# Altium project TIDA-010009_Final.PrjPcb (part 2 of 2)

## Sheet Schematic2.SchDoc
size 431 x 279 mm; Date: Not shown in title block; ApprovedBy: Not shown in title block; CheckedBy: Not shown in title block; Author: Not shown in title block; CompanyName: Not shown in title block; Engineer: Not shown in title block; Organization: Not shown in title block; Address1: Not shown in title block; Address2: Not shown in title block; Address3: Not shown in title block; Address4: Not shown in title block; DocumentNumber: 1; Revision: Use project parameter SCH_Rev; SheetNumber: 3; SheetTotal: 4; PageSetup: Record=PageOptions¦CenterHorizontal=True¦CenterVertical=True¦PrintScale=1.00¦XCorrection=1.00¦YCorrection=1.00¦PrintKind=0¦BorderSize=5000000¦LeftOffset=0¦BottomOffset=0¦Orientation=2¦PaperLength=1000¦PaperWidth=1000¦Scale=100¦PaperSource=15¦PrintQuality=600¦MediaType=1¦DitherType=10¦PaperKind=Letter¦PrintScaleMode=1
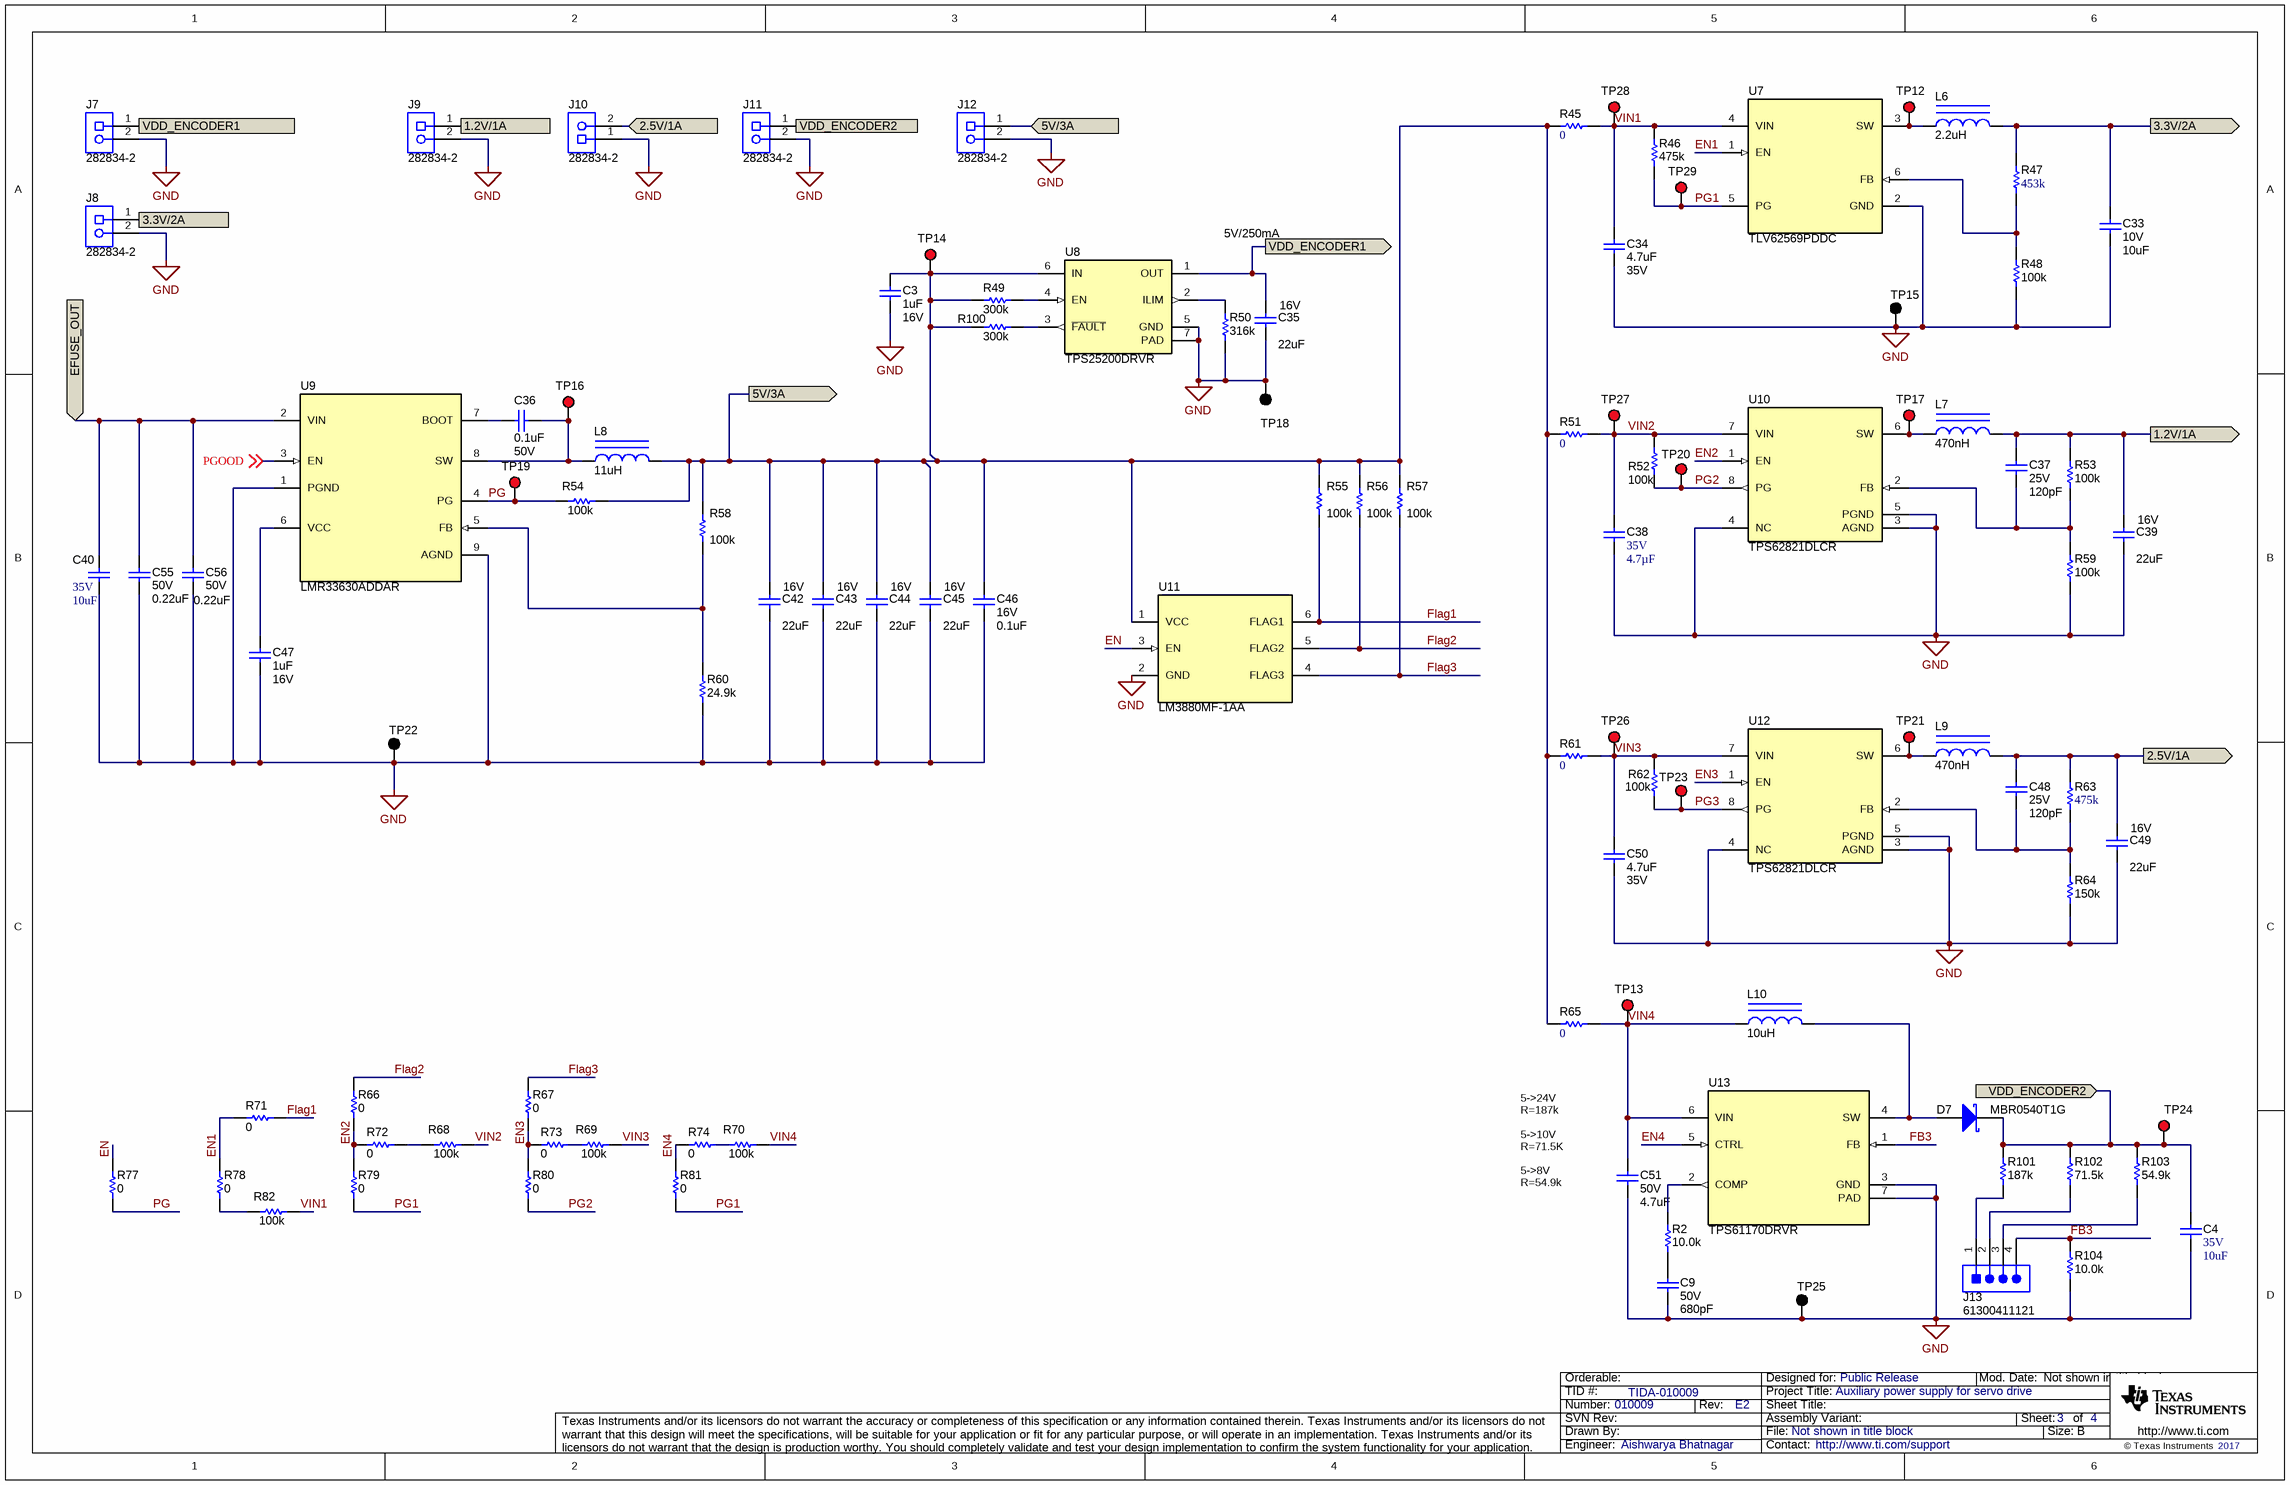
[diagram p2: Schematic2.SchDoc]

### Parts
C3  ValueDisplayed: 1uF  VDC_V: 16V  [0603]  (hidden comment: CMP-0006831-4)
C4  VDC_V: 35V  ValueDisplayed: 10uF  [1206_180]  (hidden comment: C3216X7R1V106K160AC)
C9  VDC_V: 50V  ValueDisplayed: 680pF  [0603]  (hidden comment: C0603C681K5RACTU)
C33  VDC_V: 10V  ValueDisplayed: 10uF  [0805_HV]  (hidden comment: GRM21BR71A106KE51L)
C34  ValueDisplayed: 4.7uF  VDC_V: 35V  [0805_HV]  (hidden comment: CMP-0007885-2)
C35  VDC_V: 16V  ValueDisplayed: 22uF  [1206_190]  (hidden comment: EMK316BB7226ML-T)
C36  ValueDisplayed: 0.1uF  VDC_V: 50V  [0603]  (hidden comment: CMP-0007044-5)
C37  VDC_V: 25V  ValueDisplayed: 120pF  [0201]  (hidden comment: GRM033R71E121KA01D)
C38  VDC_V: 35V  ValueDisplayed: 4.7µF  [1206_190]  (hidden comment: CGA5L1X7R1V475K160AE)
C39  VDC_V: 16V  ValueDisplayed: 22uF  [1206_190]  (hidden comment: EMK316BB7226ML-T)
C40  VDC_V: 35V  ValueDisplayed: 10uF  [1206_180]  (hidden comment: C3216X7R1V106K160AC)
C42  VDC_V: 16V  ValueDisplayed: 22uF  [1206_190]  (hidden comment: EMK316BB7226ML-T)
C43  VDC_V: 16V  ValueDisplayed: 22uF  [1206_190]  (hidden comment: EMK316BB7226ML-T)
C44  VDC_V: 16V  ValueDisplayed: 22uF  [1206_190]  (hidden comment: EMK316BB7226ML-T)
C45  VDC_V: 16V  ValueDisplayed: 22uF  [1206_190]  (hidden comment: EMK316BB7226ML-T)
C46  VDC_V: 16V  ValueDisplayed: 0.1uF  [0603]  (hidden comment: EMK107B7104KA-T)
C47  ValueDisplayed: 1uF  VDC_V: 16V  [0603]  (hidden comment: CMP-0006831-4)
C48  VDC_V: 25V  ValueDisplayed: 120pF  [0201]  (hidden comment: GRM033R71E121KA01D)
C49  VDC_V: 16V  ValueDisplayed: 22uF  [1206_190]  (hidden comment: EMK316BB7226ML-T)
C50  ValueDisplayed: 4.7uF  VDC_V: 35V  [0805_HV]  (hidden comment: CMP-0007885-2)
C51  VDC_V: 50V  ValueDisplayed: 4.7uF  [1206_190]  (hidden comment: UMK316AB7475KL-T)
C55  VDC_V: 50V  ValueDisplayed: 0.22uF  [0603]  (hidden comment: CGA3E3X7R1H224K080AB)
C56  VDC_V: 50V  ValueDisplayed: 0.22uF  [0603]  (hidden comment: CGA3E3X7R1H224K080AB)
D7  MBR0540T1G  [SOD-123]
J7  282834-2  [TEC_282834-2]
J8  282834-2  [TEC_282834-2]
J9  282834-2  [TEC_282834-2]
J10  282834-2  [TEC_282834-2]
J11  282834-2  [TEC_282834-2]
J12  282834-2  [TEC_282834-2]
J13  61300411121  [WURTH_61300411121]
L6  ValueDisplayed: 2.2uH  [LQH5BPN_20]  (hidden comment: LQH5BPN2R2NT0L)
L7  ValueDisplayed: 470nH  [XFL4015]  (hidden comment: XFL4015-471MEC)
L8  ValueDisplayed: 11uH  [WE-PDF_1064]  (hidden comment: 7447798111)
L9  ValueDisplayed: 470nH  [XFL4015]  (hidden comment: XFL4015-471MEC)
L10  ValueDisplayed: 10uH  [FDSD0420]  (hidden comment: FDSD0420-H-100M)
R2  ValueDisplayed: 10.0k  [0603]  (hidden comment: RG1608P-103-B-T5)
R45  ValueDisplayed: 0  [0805_HV]  (hidden comment: ERJ-6GEY0R00V)
R46  ValueDisplayed: 475k  [0805_HV]  (hidden comment: RR1220P-4753-D-M)
R47  ValueDisplayed: 453k  [0603]  (hidden comment: RT0603DRE07453KL)
R48  ValueDisplayed: 100k  [0603]  (hidden comment: ERA-3AEB104V)
R49  ValueDisplayed: 300k  [0603]  (hidden comment: RG1608P-304-B-T5)
R50  ValueDisplayed: 316k  [0603]  (hidden comment: RC0603FR-07316KL)
R51  ValueDisplayed: 0  [0805_HV]  (hidden comment: ERJ-6GEY0R00V)
R52  ValueDisplayed: 100k  [0603]  (hidden comment: ERA-3AEB104V)
R53  ValueDisplayed: 100k  [0603]  (hidden comment: ERA-3AEB104V)
R54  ValueDisplayed: 100k  [0603]  (hidden comment: ERA-3AEB104V)
R55  ValueDisplayed: 100k  [0603]  (hidden comment: ERA-3AEB104V)
R56  ValueDisplayed: 100k  [0603]  (hidden comment: ERA-3AEB104V)
R57  ValueDisplayed: 100k  [0603]  (hidden comment: ERA-3AEB104V)
R58  ValueDisplayed: 100k  [0603]  (hidden comment: ERA-3AEB104V)
R59  ValueDisplayed: 100k  [0603]  (hidden comment: ERA-3AEB104V)
R60  ValueDisplayed: 24.9k  [0603]  (hidden comment: RT0603BRD0724K9L)
R61  ValueDisplayed: 0  [0805_HV]  (hidden comment: ERJ-6GEY0R00V)
R62  ValueDisplayed: 100k  [0603]  (hidden comment: ERA-3AEB104V)
R63  ValueDisplayed: 475k  [0603]  (hidden comment: RT0603DRE07475KL)
R64  ValueDisplayed: 150k  [0603]  (hidden comment: RT0603BRD07150KL)
R65  ValueDisplayed: 0  [0805_HV]  (hidden comment: ERJ-6GEY0R00V)
R66  ValueDisplayed: 0  [0603]  (hidden comment: RMCF0603ZT0R00)
R67  ValueDisplayed: 0  [0603]  (hidden comment: RMCF0603ZT0R00)
R68  ValueDisplayed: 100k  [0603]  (hidden comment: ERA-3AEB104V)
R69  ValueDisplayed: 100k  [0603]  (hidden comment: ERA-3AEB104V)
R70  ValueDisplayed: 100k  [0603]  (hidden comment: ERA-3AEB104V)
R71  ValueDisplayed: 0  [0603]  (hidden comment: RMCF0603ZT0R00)
R72  ValueDisplayed: 0  [0603]  (hidden comment: RMCF0603ZT0R00)
R73  ValueDisplayed: 0  [0603]  (hidden comment: RMCF0603ZT0R00)
R74  ValueDisplayed: 0  [0603]  (hidden comment: RMCF0603ZT0R00)
R77  ValueDisplayed: 0  [0603]  (hidden comment: RMCF0603ZT0R00)
R78  ValueDisplayed: 0  [0603]  (hidden comment: RMCF0603ZT0R00)
R79  ValueDisplayed: 0  [0603]  (hidden comment: RMCF0603ZT0R00)
R80  ValueDisplayed: 0  [0603]  (hidden comment: RMCF0603ZT0R00)
R81  ValueDisplayed: 0  [0603]  (hidden comment: RMCF0603ZT0R00)
R82  ValueDisplayed: 100k  [0603]  (hidden comment: ERA-3AEB104V)
R100  ValueDisplayed: 300k  [0603]  (hidden comment: RG1608P-304-B-T5)
R101  ValueDisplayed: 187k  [0603]  (hidden comment: CRCW0603187KFKEA)
R102  ValueDisplayed: 71.5k  [0603]  (hidden comment: CRCW060371K5FKEA)
R103  ValueDisplayed: 54.9k  [0603]  (hidden comment: CRCW060354K9FKEA)
R104  ValueDisplayed: 10.0k  [0603]  (hidden comment: RG1608P-103-B-T5)
TP12  5000  [Keystone5000]  (value not drawn)
TP13  5000  [Keystone5000]  (value not drawn)
TP14  5000  [Keystone5000]  (value not drawn)
TP15  5001  [Keystone5001]  (value not drawn)
TP16  5000  [Keystone5000]  (value not drawn)
TP17  5000  [Keystone5000]  (value not drawn)
TP18  5001  [Keystone5001]  (value not drawn)
TP19  5000  [Keystone5000]  (value not drawn)
TP20  5000  [Keystone5000]  (value not drawn)
TP21  5000  [Keystone5000]  (value not drawn)
TP22  5001  [Keystone5001]  (value not drawn)
TP23  5000  [Keystone5000]  (value not drawn)
TP24  5000  [Keystone5000]  (value not drawn)
TP25  5001  [Keystone5001]  (value not drawn)
TP26  5000  [Keystone5000]  (value not drawn)
TP27  5000  [Keystone5000]  (value not drawn)
TP28  5000  [Keystone5000]  (value not drawn)
TP29  5000  [Keystone5000]  (value not drawn)
U7  TLV62569PDDC  [DDC0006A_N]
U8  TPS25200DRVR  [DRV0006A]
U9  LMR33630ADDAR  [DDA0008J]
U10  TPS62821DLCR  [DLC0008A]
U11  LM3880MF-1AA  [DBV0006A_N]
U12  TPS62821DLCR  [DLC0008A]
U13  TPS61170DRVR  [DRV0006A]

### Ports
1.2V/1A (in), 1.2V/1A (out), 2.5V/1A (in), 2.5V/1A (out), 3.3V/2A (in), 3.3V/2A (out), 5V/3A (in), 5V/3A (out), EFUSE_OUT (in), VDD_ENCODER1 (in), VDD_ENCODER1 (out), VDD_ENCODER2 (in)

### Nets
GND: C3.2 C4.2 C9.2 C33.2 C34.2 C35.2 C38.2 C39.2 C40.2 C42.2 C43.2 C44.2 C45.2 C46.2 C47.2 C49.2 C50.2 C51.2 C55.2 C56.2 J7.2 J8.2 J9.2 J10.1 J11.2 J12.2 R48.1 R50.1 R59.1 R60.1 R64.1 R104.1 TP15.1 TP18.1 TP22.1 TP25.1 U7.2(GND) U8.5(GND) U8.7(PAD) U9.1(PGND) U9.9(AGND) U10.3(AGND) U10.4(NC) U10.5(PGND) U11.2(GND) U12.3(AGND) U12.4(NC) U12.5(PGND) U13.3(GND) U13.7(PAD)
1.2V/1A: C37.1 C39.1 J9.1 L7.2 R53.2 ; port 1.2V/1A
2.5V/1A: C48.1 C49.1 J10.2 L9.2 R63.2 ; port 2.5V/1A
3.3V/2A: C33.1 J8.1 L6.2 R47.2 ; port 3.3V/2A
5V/3A: C3.1 C42.1 C43.1 C44.1 C45.1 C46.1 J12.1 L8.2 R45.1 R49.1 R51.1 R54.1 R55.2 R56.2 R57.2 R58.2 R61.1 R65.1 R100.1 TP14.1 U8.6(IN) U11.1(VCC) ; port 5V/3A
EFUSE_OUT: C40.1 C55.1 C56.1 U9.2(VIN) ; port EFUSE_OUT
EN: R77.1 U11.3(EN)
EN1: R71.1 R78.1 U7.1(EN)
EN2: R66.2 R72.1 R79.1 U10.1(EN)
EN3: R67.2 R73.1 R80.1 U12.1(EN)
EN4: R74.1 R81.1 U13.5(CTRL)
FB3: J13.4 R104.2 U13.1(FB)
Flag1: R55.1 R71.2 U11.6(FLAG1)
Flag2: R56.1 R66.1 U11.5(FLAG2)
Flag3: R57.1 R67.1 U11.4(FLAG3)
PG: R54.2 R77.2 TP19.1 U9.4(PG)
PG1: R46.1 R79.2 R81.2 TP29.1 U7.5(PG)
PG2: R52.2 R80.2 TP20.1 U10.8(PG)
PG3: R62.2 TP23.1 U12.8(PG)
PGOOD: U9.3(EN) ; off-sheet PGOOD
VDD_ENCODER1: C35.1 J7.1 U8.1(OUT) ; port VDD_ENCODER1
VDD_ENCODER2: C4.1 D7.1(K) J11.1 R101.2 R102.2 R103.2 TP24.1 ; port VDD_ENCODER2
VIN1: C34.1 R45.2 R46.2 R82.1 TP28.1 U7.4(VIN)
VIN2: C38.1 R51.2 R52.1 R68.1 TP27.1 U10.7(VIN)
VIN3: C50.1 R61.2 R62.1 R69.1 TP26.1 U12.7(VIN)
VIN4: C51.1 L10.1 R65.2 R70.1 TP13.1 U13.6(VIN)
NetC9_1: C9.1 R2.1
NetC36_1: C36.1 U9.7(BOOT)
NetC36_2: C36.2 L8.1 TP16.1 U9.8(SW)
NetC37_2: C37.2 R53.1 R59.2 U10.2(FB)
NetC47_1: C47.1 U9.6(VCC)
NetC48_2: C48.2 R63.1 R64.2 U12.2(FB)
NetD7_2: D7.2(A) L10.2 U13.4(SW)
NetJ13_1: J13.1 R101.1
NetJ13_2: J13.2 R102.1
NetJ13_3: J13.3 R103.1
NetL6_1: L6.1 TP12.1 U7.3(SW)
NetL7_1: L7.1 TP17.1 U10.6(SW)
NetL9_1: L9.1 TP21.1 U12.6(SW)
NetR2_2: R2.2 U13.2(COMP)
NetR47_1: R47.1 R48.2 U7.6(FB)
NetR49_2: R49.2 U8.4(EN)
NetR50_2: R50.2 U8.2(ILIM)
NetR58_1: R58.1 R60.2 U9.5(FB)
NetR68_2: R68.2 R72.2
NetR69_2: R69.2 R73.2
NetR70_2: R70.2 R74.2
NetR78_2: R78.2 R82.2
NetR100_2: R100.2 U8.3(~{FAULT})

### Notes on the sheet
- 5V/250mA
- (near C51) 5->24V
  R=187k
  5->10V
  R=71.5K
  5->8V
  R=54.9k

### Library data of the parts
C3 C47 = CMP-0006831-4: CAP, CERM, 1 uF, 16 V, +/- 10%, X7R, 0603; PartNumber: 885012206052; Manufacturer: Wurth Elektronik; Polarized: N; Value: 1uF; U/M: EA; Cap_F: 1µF; Value1: Unknown; TaMin_C: -55°C; TaMax_C: 125°C; SizeArea_mm2: 1.28; SizeAreaWB_mm2: 4.68; SizeX_mm: 1.6; SizeY_mm: 0.8; SizeZ_mm: 1; AEC Category: Q200
C4 C40 = CMP-0008705-2: CAP, CERM, 10 uF, 35 V, +/- 10%, X7R, 1206; Manufacturer: TDK; TaMin_C: -55°C; ESR_ohm: 2.229m; Polarized: N; SizeAreaWB_mm2: 10.92; Value1: 0.002229 ohm; U/M: EA; Value: 10uF; TaMax_C: 125°C; SizeZ_mm: 1.8; SizeX_mm: 3.2; SizeY_mm: 1.6; SizeArea_mm2: 5.12; Cap_F: 10µF; IRMS_A: 4.85932A; AEC Category: Q200
C9 = CMP-0006960-4: CAP, CERM, 680 pF, 50 V, +/- 10%, X7R, 0603; Manufacturer: Kemet; TaMin_C: -55°C; Polarized: N; SizeAreaWB_mm2: 4.68; Value1: Unknown; U/M: EA; Value: 680pF; TaMax_C: 125°C; SizeZ_mm: 1; SizeX_mm: 1.6; SizeY_mm: 0.8; SizeArea_mm2: 1.28; AEC Category: Q200
C33 = CMP-0008315-2: CAP, CERM, 10 uF, 10 V, +/- 10%, X7R, 0805; Manufacturer: MuRata; TaMin_C: -55°C; ESR_ohm: 3m; Polarized: N; SizeAreaWB_mm2: 6.75; Value1: 0.003 ohm; U/M: EA; Value: 10uF; TaMax_C: 125°C; SizeZ_mm: 1.45; SizeX_mm: 2; SizeY_mm: 1.25; Cap_Case: 0805; SizeArea_mm2: 2.5; CompType: Capacitor; Cap_F: 10µF; AEC Category: Q200
C34 C50 = CMP-0007885-2: CAP, CERM, 4.7 uF, 35 V, +/- 10%, X7R, 0805; PartNumber: C2012X7R1V475K125AC; Manufacturer: TDK; Polarized: N; Value: 4.7uF; U/M: EA; Cap_F: 4.7µF; ESR_ohm: 2.346m; Value1: 0.002346 ohm; IRMS_A: 4.26021A; TaMin_C: -55°C; TaMax_C: 125°C; Cap_Case: 0805; AEC Category: Q200; SizeArea_mm2: 2.5; SizeAreaWB_mm2: 6.75; SizeX_mm: 2; SizeY_mm: 1.25; SizeZ_mm: 1.45
C35 C39 C42-C45 C49 = CMP-0008805-2: CAP, CERM, 22 uF, 16 V, +/- 20%, X7R, 1206_190; Manufacturer: Taiyo Yuden; TaMin_C: -55°C; Polarized: N; SizeAreaWB_mm2: 10.92; Value1: Unknown; U/M: EA; Value: 22uF; TaMax_C: 125°C; SizeZ_mm: 1.9; SizeX_mm: 3.2; SizeY_mm: 1.6; Cap_Case: 1206; SizeArea_mm2: 5.12; Cap_F: 22µF; AEC Category: Q200
C36 = CMP-0007044-5: CAP, CERM, 0.1 uF, 50 V, +/- 10%, X7R, 0603; PartNumber: C1608X7R1H104K080AA; Manufacturer: TDK; Polarized: N; CompType: Capacitor; Value: 0.1uF; U/M: EA; Cap_F: 100nF; ESR_ohm: 0.0296; Value1: 0.0296 ohm; IRMS_A: 9.7199dA; TaMin_C: -55°C; TaMax_C: 125°C; SizeArea_mm2: 1.28; SizeAreaWB_mm2: 4.68; SizeX_mm: 1.6; SizeY_mm: 0.8; SizeZ_mm: 1; AEC Category: Q200
C37 C48 = CMP-0009765-1: CAP, CERM, 120 pF, 25 V, +/- 10%, X7R, 0201; Manufacturer: MuRata; TaMin_C: -55°C; Polarized: N; SizeAreaWB_mm2: 2.08; Value1: Unknown; U/M: EA; Value: 120pF; TaMax_C: 125°C; SizeZ_mm: 0.26; SizeX_mm: 0.6; SizeY_mm: 0.3; SizeArea_mm2: 0.18; AEC Category: Q200
C38 = CMP-0081201-1: CAP, CERM, 4.7 µF, 35 V,+/- 10%, X7R, AEC-Q200 Grade 1, 1206; Manufacturer: TDK; TaMin_C: -55°C; Polarized: N; SizeAreaWB_mm2: 10.92; U/M: EA; Value: 4.7uF; TaMax_C: 125°C; SizeZ_mm: 1.9; SizeX_mm: 3.2; SizeY_mm: 1.6; Cap_Case: 1206; SizeArea_mm2: 5.12; AEC Qualified: Y; AEC Grade: 1; AEC Category: Q200
C46 = CMP-0007119-4: CAP, CERM, 0.1 uF, 16 V, +/- 10%, X7R, 0603; Manufacturer: Taiyo Yuden; TaMin_C: -55°C; Polarized: N; SizeAreaWB_mm2: 4.68; Value1: Unknown; U/M: EA; Value: 0.1uF; TaMax_C: 125°C; SizeZ_mm: 1; SizeX_mm: 1.6; SizeY_mm: 0.8; SizeArea_mm2: 1.28; CompType: Capacitor; Cap_F: 100nF; AEC Category: Q200
C51 = CMP-0009026-2: CAP, CERM, 4.7 uF, 50 V, +/- 10%, X7R, 1206_190; Manufacturer: Taiyo Yuden; TaMin_C: -55°C; Polarized: N; SizeAreaWB_mm2: 10.92; Value1: Unknown; U/M: EA; Value: 4.7uF; TaMax_C: 125°C; SizeZ_mm: 1.9; SizeX_mm: 3.2; SizeY_mm: 1.6; Cap_Case: 1206; SizeArea_mm2: 5.12; CompType: Capacitor; Cap_F: 4.7µF; AEC Category: Q200
C55 C56 = CMP-0007094-5: CAP, CERM, 0.22 uF, 50 V, +/- 10%, X7R, AEC-Q200 Grade 1, 0603; Manufacturer: TDK; TaMin_C: -55°C; ESR_ohm: 0.021699; Polarized: N; SizeAreaWB_mm2: 4.68; Value1: 0.021699 ohm; U/M: EA; Value: 0.22uF; TaMax_C: 125°C; SizeZ_mm: 1; SizeX_mm: 1.6; SizeY_mm: 0.8; SizeArea_mm2: 1.28; AEC Qualified: Y; Cap_F: 220nF; IRMS_A: 1.12496A; AEC Category: Q200
D7 = CMP-0028526-2: Diode, Schottky, 40 V, 0.5 A, SOD-123; Manufacturer: ON Semiconductor; Green_REACh: Passed; SizeY_mm: 1.7; Io_A: 5dA; SizeArea_mm2: 6.545; RJC_CperW: 118; Green_Lifecycle: Active; Vr_V: 40V; Vf_V: 5.1dV; TJmax_C: 150°C; AEC Category: Q101; SizeAreaWB_mm2: 13.095; Value1: 0.5A; SizeZ_mm: 1.35; SizeX_mm: 3.85; Value2: 0.51V; Value: 40V
J7-J12 = CMP-0054974-1: Terminal Block, 2x1, 2.54mm, TH; Manufacturer: TE Connectivity; CNHeader: FALSE; Green_Lifecycle: Active; Green_REACh: Passed; CT: TRUE
J13 = CMP-0054798-1: Header, 2.54 mm, 4x1, Gold, TH; Manufacturer: Wurth Elektronik; CNHeader: TRUE; CT: FALSE
L6 = CMP-0058727-1: Inductor, Wirewound, Ferrite, 2.2 uH, 2.6 A, 0.036 ohm, SMD; Manufacturer: MuRata; Isat: 4A @ 30% inductance drop; Irms: 2.6A @ 40C rise; SizeAreaWB_mm2: 34.81; DCR_ohm: 0.036; Value: 2.2uH; Imax_A: 2.6A; SizeZ_mm: 2.2; SizeX_mm: 4.9; SizeArea_mm2: 24.01; Ind_H: 2.2µH; AEC Qualified: N; AEC Category: Q200
L7 L9 = CMP-0061147-1: Inductor, Shielded, Composite, 470 nH, 3.5 A, 0.0076 ohm, SMD; Manufacturer: Coilcraft; Isat: 3.5A @ 10% inductance drop; Irms: 9.1A @ 20C rise; Green_Lifecycle: Not Set; SizeAreaWB_mm2: 28.09; DCR_ohm: 7.6m; Green_REACh: Incomplete; Value: 470nH; Imax_A: 3.5A; SizeZ_mm: 1.6; SizeX_mm: 4.3; SizeArea_mm2: 18.49; AEC Category: Q200
L8 = CMP-0064666-2: Inductor, Shielded, Metal Composite, 11 uH, 5.3 A, 0.014 ohm, SMD; Manufacturer: Wurth Elektronik; Isat: 5.3A @ 10% inductance drop; Irms: 6.9A @ 40C rise; Green_Lifecycle: Active; SizeAreaWB_mm2: 148.84; DCR_ohm: 0.014; Green_REACh: Passed; Value: 11uH; Imax_A: 5.3A; SizeZ_mm: 6.4; SizeX_mm: 10.2; SizeArea_mm2: 104.04; Ind_H: 11µH; AEC Category: Q200
L10 = CMP-0058995-1: Inductor, Shielded, Powdered Iron, 10 uH, 2 A, 0.2 ohm, SMD; Manufacturer: MuRata Toko; Isat: 3.3A @ 30% inductance drop; Irms: 2A @ 40C rise; Green_Lifecycle: Not Set; SizeAreaWB_mm2: 27.04; DCR_ohm: 2d; Green_REACh: Incomplete; Value1: 0.2 ohm; Value: 10uH; Imax_A: 2A; SizeZ_mm: 2; SizeX_mm: 4.2; SizeArea_mm2: 17.64; Ind_H: 10µH; AEC Category: Q200
R2 R104 = CMP-0023404-3: RES, 10.0 k, 0.1%, 0.1 W, 0603; Manufacturer: Susumu Co Ltd; Power_W: 100mW; TempCo: 25 ppm/C; Value_Code: 10k0; U/M: EA; Value: 10.0k; EIA_Code: E192; Res_ohm: 10k; SizeX_mm: 1.6; SizeY_mm: 0.8; SizeZ_mm: 1; Value2: 0.1W; SizeArea_mm2: 1.28; VDC_V: 75V; AEC Category: Q200
R45 R51 R61 R65 = CMP-0020616-3: RES, 0, 5%, 0.125 W, AEC-Q200 Grade 0, 0805; Manufacturer: Panasonic; Power_W: 125mW; TempCo: 600 ppm/C; Value_Code: 0000; Value: 0; EIA_Code: E24; SizeX_mm: 2; SizeY_mm: 1.25; SizeZ_mm: 1.45; Value2: 0.125W; SizeArea_mm2: 2.5; AEC Qualified: Y; VDC_V: 150V; AEC Category: Q200; SizeAreaWB_mm2: 6.75
R46 = CMP-0019302-2: RES, 475 k, 0.5%, 0.1 W, 0805; Manufacturer: Susumu Co Ltd; Power_W: 100mW; TempCo: 25 ppm/C; U/M: EA; Value: 475k; EIA_Code: E192; SizeX_mm: 2; SizeY_mm: 1.25; SizeZ_mm: 1.45; Value2: 0.1W; SizeArea_mm2: 2.5; VDC_V: 100V; AEC Category: Q200
R47 = CMP-0025299-2: RES, 453 k, 0.5%, 0.1 W, 0603; Manufacturer: Yageo America; Power_W: 100mW; TempCo: 50 ppm/C; U/M: EA; Value: 453k; EIA_Code: E192; SizeX_mm: 1.6; SizeY_mm: 0.8; SizeZ_mm: 1; Value2: 0.1W; SizeArea_mm2: 1.28; VDC_V: 75V; AEC Category: Q200
R48 R52-R59 R62 R68 R70 R82 = CMP-0023363-3: RES, 100 k, 0.1%, 0.1 W, AEC-Q200 Grade 0, 0603; Manufacturer: Panasonic; Power_W: 100mW; TempCo: 25 ppm/C; U/M: EA; Value: 100k; EIA_Code: E192; SizeX_mm: 1.6; SizeY_mm: 0.8; SizeZ_mm: 1; Value2: 0.1W; SizeArea_mm2: 1.28; AEC Qualified: Y; VDC_V: 75V; AEC Grade: 0; AEC Category: Q200
R49 R100 = CMP-0023509-3: RES, 300 k, 0.1%, 0.1 W, 0603; Manufacturer: Susumu Co Ltd; Power_W: 100mW; TempCo: 25 ppm/C; U/M: EA; Value: 300k; SizeX_mm: 1.6; SizeY_mm: 0.8; SizeZ_mm: 1; Value2: 0.1W; SizeArea_mm2: 1.28; VDC_V: 75V; AEC Category: Q200
R50 = CMP-0023024-4: RES, 316 k, 1%, 0.1 W, 0603; Manufacturer: Yageo; Power_W: 100mW; TempCo: 100 ppm/C; Value: 316k; EIA_Code: E96; SizeX_mm: 1.6; SizeY_mm: 0.8; SizeZ_mm: 1; Value2: 0.1W; SizeArea_mm2: 1.28; AEC Qualified: N; VDC_V: 75V; AEC Category: Q200; SizeAreaWB_mm2: 4.68
R60 = CMP-0023990-3: RES, 24.9 k, 0.1%, 0.1 W, 0603; Manufacturer: Yageo America; Power_W: 100mW; TempCo: 25 ppm/C; Value_Code: 24k9; U/M: EA; Value: 24.9k; EIA_Code: E192; SizeX_mm: 1.6; SizeY_mm: 0.8; SizeZ_mm: 1; Value2: 0.1W; SizeArea_mm2: 1.28; CompType: Resistor; VDC_V: 75V; AEC Category: Q200
R63 = CMP-0025313-3: RES, 475 k, 0.5%, 0.1 W, 0603; Manufacturer: Yageo America; Power_W: 100mW; TempCo: 50 ppm/C; U/M: EA; Value: 475k; EIA_Code: E192; SizeX_mm: 1.6; SizeY_mm: 0.8; SizeZ_mm: 1; Value2: 0.1W; SizeArea_mm2: 1.28; VDC_V: 75V; AEC Category: Q200
R64 = CMP-0023766-3: RES, 150 k, 0.1%, 0.1 W, 0603; Manufacturer: Yageo America; Power_W: 100mW; TempCo: 25 ppm/C; U/M: EA; Value: 150k; EIA_Code: E192; SizeX_mm: 1.6; SizeY_mm: 0.8; SizeZ_mm: 1; Value2: 0.1W; SizeArea_mm2: 1.28; VDC_V: 75V; AEC Category: Q200
R66 R67 R71-R74 R77-R81 = CMP-0023343-3: RES, 0, 1%, 0.1 W, AEC-Q200 Grade 0, 0603; Manufacturer: Stackpole Electronics Inc; Power_W: 100mW; TempCo: ppm/C; U/M: EA; Value: 0; SizeX_mm: 1.6; SizeY_mm: 0.8; SizeZ_mm: 1; Value2: 0.1W; SizeArea_mm2: 1.28; AEC Qualified: Y; AEC Category: Q200
R69 = CMP-0023363-3: RES, 100 k, 0.1%, 0.1 W, AEC-Q200 Grade 0, 0603; Manufacturer: Panasonic; Power_W: 100mW; TempCo: 25 ppm/C; U/M: EA; Value: 100k; EIA_Code: E192; SizeX_mm: 1.6; SizeY_mm: 0.8; SizeZ_mm: 1; Value2: 0.1W; SizeArea_mm2: 1.28; CompType: Resistor; AEC Qualified: Y; VDC_V: 75V; AEC Grade: 0; AEC Category: Q200
R101 = CMP-0022095-4: RES, 187 k, 1%, 0.1 W, AEC-Q200 Grade 0, 0603; Manufacturer: Vishay-Dale; Power_W: 100mW; TempCo: 100 ppm/C; Value: 187k; EIA_Code: E96; SizeX_mm: 1.6; SizeY_mm: 0.8; SizeZ_mm: 1; Value2: 0.1W; SizeArea_mm2: 1.28; AEC Qualified: Y; VDC_V: 75V; AEC Category: Q200; AEC Grade: 0
R102 = CMP-0022581-4: RES, 71.5 k, 1%, 0.1 W, AEC-Q200 Grade 0, 0603; Manufacturer: Vishay-Dale; Power_W: 100mW; TempCo: 100 ppm/C; Value_Code: 71k5; Value: 71.5k; EIA_Code: E96; SizeX_mm: 1.6; SizeY_mm: 0.8; SizeZ_mm: 1; Value2: 0.1W; SizeArea_mm2: 1.28; AEC Qualified: Y; VDC_V: 75V; AEC Category: Q200; AEC Grade: 0
R103 = CMP-0022494-4: RES, 54.9 k, 1%, 0.1 W, AEC-Q200 Grade 0, 0603; Manufacturer: Vishay-Dale; Power_W: 100mW; TempCo: 100 ppm/C; Value_Code: 54k9; Value: 54.9k; EIA_Code: E96; SizeX_mm: 1.6; SizeY_mm: 0.8; SizeZ_mm: 1; Value2: 0.1W; SizeArea_mm2: 1.28; AEC Qualified: Y; VDC_V: 75V; AEC Category: Q200; AEC Grade: 0
TP12-TP14 TP16 TP17 TP19-TP21 TP23 TP24 TP26-TP29 = CMP-0055137-1: Test Point, Miniature, Red, TH; Manufacturer: Keystone; CNHeader: FALSE; Green_Lifecycle: Active; Green_REACh: Passed; ContactFinish: Silver; CT: TRUE
TP15 TP18 TP22 TP25 = CMP-0055138-1: Test Point, Miniature, Black, TH; Manufacturer: Keystone; CNHeader: FALSE; Green_Lifecycle: Active; Green_REACh: Passed; ContactFinish: Silver; CT: TRUE
U7 = CMP-0013280-3: 2-A High Efficiency Step-Down Converter in SOT Package, DDC0006A (SOT-6); Manufacturer: Texas Instruments; SizeZ_mm: 0.87; SizeX_mm: 1.65; SizeY_mm: 2.95; SizeArea_mm2: 4.8675; CompType: IC; U/M: EA; SizeAreaWB_mm2: 10.4675
U8 = CMP-0074216-4: 6.5 V/2.8 A eFuse with Overvoltage Clamp, DRV0006A (WSON-6); Manufacturer: Texas Instruments; Alternate PartNumber: TPS25200DRVT; SizeX_mm: 2; CompType: IC; SizeZ_mm: 0.8; SizeArea_mm2: 4; SizeAreaWB_mm2: 9; U/M: EA; Green_Lifecycle: Active; Green_REACh: Passed
U9 = CMP-0013272-2: SIMPLE SWITCHER 3.8V to 36V 3A/2A Synchronous Step-Down Voltage Regulator, DDA0008J (SOIC-8); Manufacturer: Texas Instruments; SizeX_mm: 5.99; SizeY_mm: 4.89; CompType: IC; SizeZ_mm: 1.7; SizeArea_mm2: 29.2911; SizeAreaWB_mm2: 55.0511; U/M: EA
U10 U12 = CMP-0065148-3: 1A Step-Down Converter With 1% Accuracy, DLC0008A (VSON-HR-8); Manufacturer: Texas Instruments; SizeX_mm: 1.5; SizeY_mm: 2.0; CompType: IC; SizeZ_mm: 1.0; SizeArea_mm2: 3.0; SizeAreaWB_mm2: 7.5; AEC Category: Q200; AEC Qualified: N
U11 = CMP-0071684-1: Power Sequencer, 6-pin SOT-23, 1000 Reel; Manufacturer: Texas Instruments; CompType: MiscPower; PackageTopMarking: F20A*XTT; High-Reliability: Y; PowerWise: N
U13 = CMP-0067200-5: 1.2A Switch, High Voltage Boost Converter in 2x2mm QFN Package, DRV0006A (WSON-6); Manufacturer: Texas Instruments; Alternate PartNumber: TPS61170DRVT; SizeX_mm: 2; CompType: IC; SizeZ_mm: 0.8; SizeArea_mm2: 4; SizeAreaWB_mm2: 9; U/M: EA; Green_Lifecycle: Active; Green_REACh: Passed

## Sheet TIDA-010009_EVM_Hardware.SchDoc
size 431 x 279 mm; Date: Not shown in title block; ApprovedBy: Not shown in title block; CheckedBy: Not shown in title block; Author: Not shown in title block; CompanyName: Not shown in title block; Engineer: Not shown in title block; Organization: Not shown in title block; Address1: Not shown in title block; Address2: Not shown in title block; Address3: Not shown in title block; Address4: Not shown in title block; DocumentNumber: 1; Revision: Use project parameter SCH_Rev; SheetNumber: 4; SheetTotal: 4; PageSetup: Record=PageOptions¦CenterHorizontal=True¦CenterVertical=True¦PrintScale=1.00¦XCorrection=1.00¦YCorrection=1.00¦PrintKind=0¦BorderSize=5000000¦LeftOffset=0¦BottomOffset=0¦Orientation=2¦PaperLength=1000¦PaperWidth=1000¦Scale=100¦PaperSource=15¦PrintQuality=600¦MediaType=1¦DitherType=10¦PaperKind=Letter¦PrintScaleMode=1
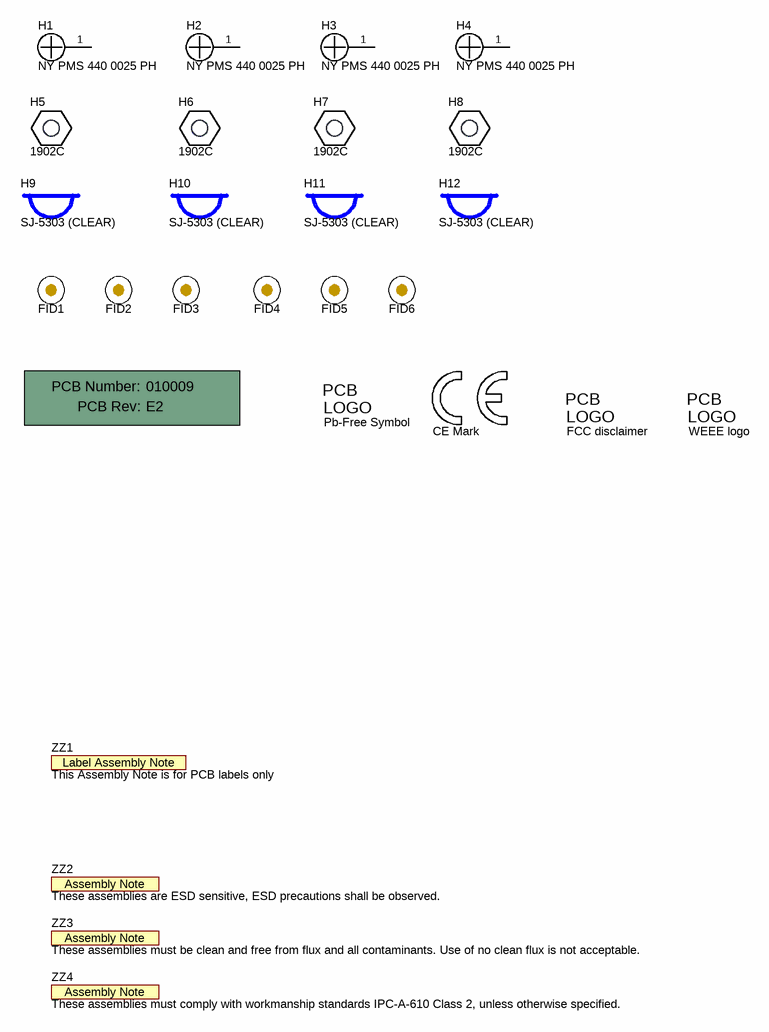
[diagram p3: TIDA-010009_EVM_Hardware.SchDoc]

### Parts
!PCB1  Printed Circuit Board  (value not drawn)  (mechanical)
FID1  Fiducial  [Fiducial10-20]  (value not drawn)
FID2  Fiducial  [Fiducial10-20]  (value not drawn)
FID3  Fiducial  [Fiducial10-20]  (value not drawn)
FID4  Fiducial  [Fiducial10-20]  (value not drawn)
FID5  Fiducial  [Fiducial10-20]  (value not drawn)
FID6  Fiducial  [Fiducial10-20]  (value not drawn)
H1  NY PMS 440 0025 PH  [NY PMS 440 0025 PH]
H2  NY PMS 440 0025 PH  [NY PMS 440 0025 PH]
H3  NY PMS 440 0025 PH  [NY PMS 440 0025 PH]
H4  NY PMS 440 0025 PH  [NY PMS 440 0025 PH]
H5  1902C  [Keystone_1902C]
H6  1902C  [Keystone_1902C]
H7  1902C  [Keystone_1902C]
H8  1902C  [Keystone_1902C]
H9  SJ-5303 (CLEAR)  [Bumpon_SJ5003Transparent]
H10  SJ-5303 (CLEAR)  [Bumpon_SJ5003Transparent]
H11  SJ-5303 (CLEAR)  [Bumpon_SJ5003Transparent]
H12  SJ-5303 (CLEAR)  [Bumpon_SJ5003Transparent]
Logo1  CE Mark  [CE_Mark_5mm]  (no BOM)
Logo3  FCC disclaimer  [FCC_disclaimer]  (no BOM)
Logo4  WEEE logo  [WEEE_Minimum]  (no BOM)
Logo5  Pb-Free Symbol  [Pb-Free_Overlay_Small]  (no BOM)
ZZ1  This Assembly Note is for PCB labels only  [AssemblyNoteLabel]  (no BOM)
ZZ2  These assemblies are ESD sensitive, ESD precautions shall be observed.  [AssemblyNote]  (no BOM)
ZZ3  These assemblies must be clean and free from flux and all contaminants. Use of no clean flux is not acceptable.  [AssemblyNote]  (no BOM)
ZZ4  These assemblies must comply with workmanship standards IPC-A-610 Class 2, unless otherwise specified.  [AssemblyNote]  (no BOM)

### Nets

Not connected (* = marked no-connect by the designer): H1 1; H2 1; H3 1; H4 1

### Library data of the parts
!PCB1 = CMP-0003618-2: Manufacturer: Any; PartNumber: 010009
FID1-FID6 = CMP-0077181-1: Fiducial mark.  There is nothing to buy or mount.
H1-H4 = CMP-0003617-1: Machine Screw, Round, #4-40 x 1/4, Nylon, Philips panhead; Manufacturer: B&F Fastener Supply; CompType: Hardware
H5-H8 = CMP-0003610-1: Standoff, Hex, 0.5"L #4-40 Nylon; Manufacturer: Keystone; CompType: Hardware
H9-H12 = CMP-0003620-1: Bumpon, Hemisphere, 0.44 X 0.20, Clear; Manufacturer: 3M
Logo1 = CMP-0074844-1: SymbolCreator: a0412235
Logo3 = CMP-0074847-1: FCC_disclaimer; Library Reference: Logo
Logo4 = CMP-0074769-1
Logo5 = CMP-0074839-1: SymbolCreator: a0412235; Library Reference: Logo
ZZ1 = CMP-0003616-3
ZZ2 = CMP-0077236-1
ZZ3 = CMP-0077237-1
ZZ4 = CMP-0077238-1

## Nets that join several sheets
GND: Schematic1 (42 pins), Schematic2 (50 pins)
EFUSE_OUT: Schematic1 (15 pins), Schematic2 (C40.1 C55.1 C56.1 U9.2)
PGOOD: Schematic1 (R18.1 U3.16 U4.4), Schematic2 (U9.3)

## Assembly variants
001: not fitted D1 FID1 FID2 FID3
